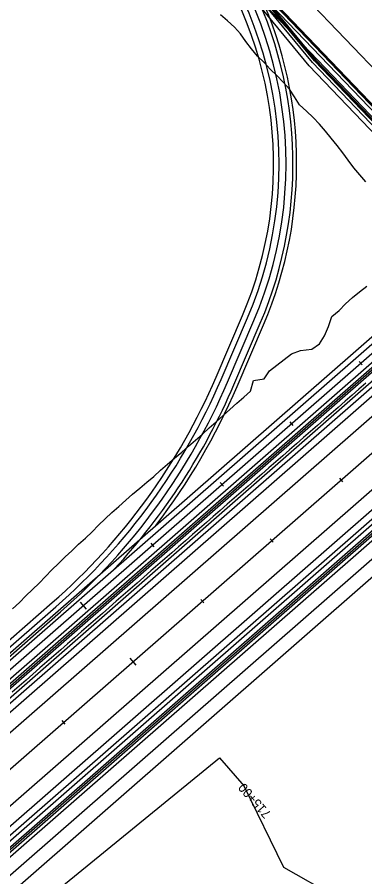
# Model space of a CAD drawing. Extents: x 1300404 to 1323571, y 234004 to 252077.
# Drawn here: x 1310184 to 1310561, y 240349 to 241283 of the extents above; entities that cross this region are included whole.
import ezdxf

# ---------------------------------------------------------------- set-up
doc = ezdxf.new("R2010")
doc.units = 0
for name, color, linetype in [('R_Barrier Wall', 7, 'Continuous'), ('R_Const Limits', 7, 'Continuous'), ('R_Curb', 7, 'Continuous'), ('R_Draft', 7, 'Continuous'), ('R_Flooplain', 7, 'Continuous'), ('R_Future', 7, 'Continuous'), ('R_Horz Alg Major Ticks', 7, 'Continuous'), ('R_Horz Alg Minor Ticks', 7, 'Continuous'), ('R_Horz Alg Station Annot', 7, 'Continuous'), ('R_Lane Edge', 7, 'Continuous'), ('R_Proposed', 7, 'Continuous'), ('R_Shoulder', 7, 'Continuous'), ('R_Sidewalk Edge', 7, 'Continuous')]:
    doc.layers.add(name, color=color, linetype=linetype)

msp = doc.modelspace()

# ---------------------------------------------------------------- linework, layer by layer
at = {"layer": 'R_Barrier Wall'}
for p, q in [((1309593.62, 240046.84), (1310899.19, 241188.45)), ((1309594.93, 240045.34), (1310900.51, 241186.94))]:
    msp.add_line(p, q, dxfattribs=at)
at = {"layer": 'R_Const Limits'}
for points in [[(1310562.4, 241103.84), (1310555.79, 241111.35), (1310549.4, 241119.07), (1310543.4, 241127.17), (1310537.44, 241135.31), (1310531.38, 241143.35), (1310524.96, 241151.04), (1310518.56, 241158.76), (1310511.97, 241166.29), (1310505.12, 241173.58), (1310497.93, 241180.54), (1310490.48, 241187.26), (1310485.18, 241196.02), (1310479.41, 241204.33), (1310472.78, 241211.83), (1310465.98, 241219.17), (1310458.63, 241225.97), (1310452.03, 241233.49), (1310444.72, 241240.34), (1310438.43, 241248.16), (1310432.36, 241256.19), (1310426.55, 241264.47), (1310419.75, 241271.8), (1310412.25, 241278.47), (1310404.66, 241285.05)], [(1310179.04, 240640.12), (1310186.38, 240646.92), (1310193.47, 240654), (1310200.6, 240661.04), (1310207.87, 240667.92), (1310214.89, 240675.08), (1310221.79, 240682.38), (1310229.01, 240689.32), (1310236.14, 240696.35), (1310243.48, 240703.15), (1310250.68, 240710.11), (1310258.01, 240716.92), (1310265.35, 240723.72), (1310272.47, 240730.76), (1310279.6, 240737.81), (1310286.93, 240744.61), (1310294.36, 240751.3), (1310301.84, 240757.94), (1310309.36, 240764.53), (1310316.99, 240771), (1310324.66, 240777.43), (1310332.34, 240783.83), (1310339.68, 240790.63), (1310347.16, 240797.26), (1310354.75, 240803.77), (1310362.59, 240810), (1310370.09, 240816.62), (1310377.59, 240823.23), (1310385.07, 240829.87), (1310392.53, 240836.53), (1310399.99, 240843.19), (1310407.43, 240849.87), (1310414.98, 240856.43), (1310422.32, 240863.23), (1310429.92, 240869.73), (1310437.19, 240876.6), (1310440.42, 240888.1), (1310452.07, 240889.97), (1310457.81, 240898.6), (1310465.82, 240904.62), (1310473.74, 240910.77), (1310481.68, 240916.87), (1310491.57, 240920.76), (1310503.68, 240922.1), (1310512.02, 240927.75), (1310517.74, 240936.4), (1310522, 240946.72), (1310525.69, 240957.69), (1310533.3, 240964.18), (1310540.29, 240971.38), (1310547.81, 240977.97), (1310555.56, 240984.3), (1310563.36, 240990.58)], [(1310562.52, 240885.19), (1310554.99, 240878.61), (1310547.46, 240872.03), (1310539.94, 240865.44), (1310532.41, 240858.86), (1310524.88, 240852.28), (1310517.35, 240845.7), (1310509.82, 240839.11), (1310502.3, 240832.53), (1310494.77, 240825.95), (1310487.24, 240819.37), (1310479.71, 240812.78), (1310472.18, 240806.2), (1310464.66, 240799.62), (1310457.13, 240793.04), (1310449.6, 240786.45), (1310442.07, 240779.87), (1310434.54, 240773.29), (1310427.02, 240766.71), (1310419.49, 240760.12), (1310411.96, 240753.54), (1310404.43, 240746.96), (1310396.9, 240740.38), (1310389.38, 240733.79), (1310381.85, 240727.21), (1310374.32, 240720.63), (1310366.79, 240714.05), (1310359.26, 240707.46), (1310351.74, 240700.88), (1310344.21, 240694.3), (1310336.68, 240687.72), (1310329.15, 240681.13), (1310321.62, 240674.55), (1310314.1, 240667.97), (1310306.57, 240661.39), (1310299.04, 240654.8), (1310291.51, 240648.22), (1310283.98, 240641.64), (1310276.46, 240635.06), (1310268.93, 240628.47), (1310261.4, 240621.89), (1310253.87, 240615.31), (1310246.34, 240608.73), (1310238.82, 240602.14), (1310231.29, 240595.56), (1310223.76, 240588.98), (1310216.23, 240582.4), (1310208.7, 240575.81), (1310201.18, 240569.23), (1310193.65, 240562.65), (1310186.12, 240556.07), (1310178.59, 240549.48)]]:
    msp.add_lwpolyline(points, dxfattribs=at)
at = {"layer": 'R_Curb'}
for p, q in [((1310372.48, 241392.56), (1310671.99, 241078.77)), ((1310373.35, 241390.92), (1310671.61, 241078.44))]:
    msp.add_line(p, q, dxfattribs=at)
at = {"layer": 'R_Draft'}
for p, q in [((1308396.96, 238971.92), (1312368.36, 242444.53)), ((1308407.83, 238959.5), (1312379.22, 242432.11)), ((1308447.32, 238914.33), (1312418.71, 242386.94)), ((1308458.18, 238901.91), (1312429.57, 242374.52)), ((1309037.78, 239548.19), (1312137.61, 242258.71)), ((1309184.47, 239689.08), (1312131.36, 242265.86)), ((1309193.69, 239678.54), (1312140.58, 242255.32)), ((1309413.86, 239721.62), (1312065.67, 242040.38)), ((1309410.89, 239725), (1311987.97, 241978.41)), ((1309410.89, 239725), (1311987.97, 241978.41))]:
    msp.add_line(p, q, dxfattribs=at)
at = {"layer": 'R_Flooplain'}
for p, q in [((1310180.38, 240295.99), (1310403.59, 240478.31)), ((1310403.59, 240478.31), (1310430.47, 240447.32)), ((1310473.27, 240359.27), (1310430.47, 240447.32)), ((1310628.59, 240271.59), (1310473.27, 240359.27))]:
    msp.add_line(p, q, dxfattribs=at)
at = {"layer": 'R_Future'}
for p, q in [((1311714.76, 241726.24), (1309950.43, 240183.5)), ((1311716.07, 241724.73), (1309951.75, 240181.99)), ((1311717.39, 241723.23), (1309953.06, 240180.49)), ((1311720.02, 241720.22), (1309955.69, 240177.48)), ((1310412.25, 241352.34), (1310507.86, 241236.24)), ((1310500.78, 241229.89), (1310405.17, 241345.99)), ((1310504.53, 241233.21), (1310408.91, 241349.31)), ((1310506.77, 241235.21), (1310411.16, 241351.31)), ((1310411.52, 241351.65), (1310507.13, 241235.55)), ((1310504.53, 241233.21), (1310647.25, 241083.69)), ((1310506.77, 241235.21), (1310984.1, 240735.13)), ((1310506.77, 241235.21), (1310984.1, 240735.13)), ((1310507.13, 241235.55), (1310981.19, 240738.9)), ((1310507.13, 241235.55), (1310981.19, 240738.9)), ((1310507.86, 241236.24), (1310967.32, 240754.88)), ((1310507.86, 241236.24), (1310967.32, 240754.88)), ((1310500.78, 241229.89), (1310643.48, 241080.39)), ((1310399.86, 240891.49), (1310428.53, 240958.46)), ((1310405.37, 240889.13), (1310434.04, 240956.1)), ((1310412.27, 240886.18), (1310440.94, 240953.15)), ((1310419.16, 240883.23), (1310447.83, 240950.19)), ((1310422.84, 240881.65), (1310451.51, 240948.62)), ((1310616.69, 240735.53), (1309965.57, 240166.18)), ((1310582.45, 240685.67), (1309975.44, 240154.89)), ((1309920.97, 240383.56), (1310222.09, 240646.86)), ((1309924.92, 240379.04), (1310226.04, 240642.34)), ((1310097.85, 240520.29), (1310230.98, 240636.7))]:
    msp.add_line(p, q, dxfattribs=at)
for centre, radius, start, end in [((1310043.42, 241123.33), 432.42, 336.82333, 43.66667), ((1310043.42, 241123.33), 424.92, 336.82333, 43.66667), ((1310043.42, 241123.33), 418.92, 336.82333, 36.25513), ((1310043.42, 241123.33), 439.92, 336.82333, 28.66161), ((1310043.42, 241123.33), 443.92, 336.82333, 26.18643), ((1309773.83, 241159.51), 680.99, 311.16667, 336.82333), ((1309773.83, 241159.51), 686.99, 311.16667, 336.82333), ((1309773.83, 241159.51), 694.49, 311.16667, 336.82333), ((1309773.83, 241159.51), 701.99, 317.28606, 336.82333), ((1309773.83, 241159.51), 705.99, 322.59605, 336.82333)]:
    msp.add_arc(centre, radius, start, end, dxfattribs=at)
at = {"layer": 'R_Horz Alg Major Ticks'}
for points in [[(1310252.28, 240647.36), (1310258.87, 240639.83)], [(1310306.27, 240586.3), (1310312.86, 240578.77)]]:
    msp.add_lwpolyline(points, dxfattribs=at)
at = {"layer": 'R_Horz Alg Minor Ticks'}
for points in [[(1310555.05, 240908.78), (1310558.34, 240905.01)], [(1310479.77, 240842.95), (1310483.06, 240839.19)], [(1310404.49, 240777.12), (1310407.78, 240773.36)], [(1310533.76, 240781.9), (1310537.05, 240778.13)], [(1310329.21, 240711.3), (1310332.5, 240707.54)], [(1310458.48, 240716.07), (1310461.77, 240712.31)], [(1310383.2, 240650.25), (1310386.49, 240646.48)], [(1310232.64, 240518.6), (1310235.93, 240514.83)]]:
    msp.add_lwpolyline(points, dxfattribs=at)
at = {"layer": 'R_Lane Edge'}
for p, q in [((1310412.25, 241352.34), (1311200.16, 240526.88)), ((1309579.79, 240062.65), (1310885.34, 241204.23)), ((1309589.67, 240051.36), (1310895.24, 241192.96))]:
    msp.add_line(p, q, dxfattribs=at)
at = {"layer": 'R_Proposed'}
for p, q in [((1308463.14, 238968.01), (1312793.8, 242754.77)), ((1308427.57, 238936.91), (1312398.96, 242409.52)), ((1309180.37, 239595.16), (1312398.96, 242409.52)), ((1309180.37, 239595.16), (1312398.96, 242409.52)), ((1309180.37, 239595.16), (1312051.46, 242105.66)), ((1310151.78, 241665.77), (1311952.58, 239779.15)), ((1310165.59, 241651.3), (1311952.63, 239779.09)), ((1310165.59, 241651.3), (1311952.63, 239779.09)), ((1310223.05, 241550.56), (1311374.36, 240344.37)), ((1309584.71, 240056.98), (1310889.67, 241198.05))]:
    msp.add_line(p, q, dxfattribs=at)
at = {"layer": 'R_Shoulder'}
for p, q in [((1309575.85, 240067.17), (1310881.38, 241208.74)), ((1309592.3, 240048.35), (1310897.87, 241189.95))]:
    msp.add_line(p, q, dxfattribs=at)
at = {"layer": 'R_Sidewalk Edge'}
for p, q in [((1310378.2, 241381.49), (1310655.54, 241090.93)), ((1310385.11, 241367.02), (1310651.77, 241087.64))]:
    msp.add_line(p, q, dxfattribs=at)

# ---------------------------------------------------------------- texts
at = {"layer": 'R_Horz Alg Station Annot'}
msp.add_text('715+00', height=10, rotation=131.16667, dxfattribs=at).set_placement((1310460.18, 240417.89))

doc.saveas('drawing.dxf')
